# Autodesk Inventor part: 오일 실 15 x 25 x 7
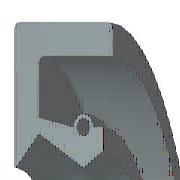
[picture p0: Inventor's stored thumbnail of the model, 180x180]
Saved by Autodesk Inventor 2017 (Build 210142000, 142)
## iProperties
Created: 2012-02
Part Number: 오일 실 15 x 25 x 7
Material: 고무
Description: 오일-실
Document SubType Name: Modeling
Standard: KS B 2804
Designer: mduedu
Standards Organization: KS
Language: ko-KR
Size Designation: D - 15 25 7
Categories: <MemberInstance><Categories><Category DisplayName="샤프트 부품" InternalName="7f7aeb1f-a693-4053-b835-cee3144e0d98" Mnemonic="SHFT"><Category DisplayName="실링" Intern
Density: 0.93 g/cm^3
Mass: 1.46464 g
Surface Area: 21.6685 cm^2
Volume: 1.57488 cm^3
Appearance: 고무 - 검은색 - 버전 1.1
IsCustomPart: 1
Author: mduedu
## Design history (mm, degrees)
revolve "본체" stored, may be unused: angle "d17" = 90 deg
revolve "스프링1" stored, may be unused: angle "d18" = 90 deg
body "Solid1"
sketch "스케치1"
  geometry: L1 (0, 12.5)-(7, 12.5); L2 (7, 10.75)-(1.75, 10.75); L3 (1.75, 9.25)-(4.9, 7.5); L4 (4.9, 7.5)-(0, 7.5); L5 (0, 0)-(9.586, 0) reference; L6 (4.9, 7.5)-(6.3, 8.375); L7 (0, 18)-(0, -3) reference; L8 (-1.941, 0)-(11.507, 0) reference; L9 (4.2, 9.6)-(1.75, 10.09); L10 (1.75, 10.09)-(1.75, 10.75); L11 (0, 12.5)-(0, 7.588); L12 (4.9, 7.5)-(0, 7.5); L13 (1.75, 9.25)-(0.152, 7.528); L14 (7, 12.5)-(7, 10.75); L15 (5.6, 9.6)-(6.3, 9.6); L16 (6.3, 9.6)-(6.3, 8.375); C1 r 0.455 at (4.9, 9.6); A1 r 0.7 centre (4.9, 9.6) between (5.6, 9.6) and (4.2, 9.6); A2 r 0.088 centre (0.088, 7.588) between (0, 7.588) and (0.152, 7.528); 1 further point
  constraints: 28 end point, 5 horizontal alignment, 5 point on line, 4 point on circle, 4 vertical alignment, 3 centre point, 3 tangent, 2 collinear, 2 horizontal, 2 perpendicular, 1 coincident, 1 parallel
  dimensions: "d0" = 25 diameter of L1 L5 (= SD2); "d1" = 1.75 distance of L1.end L2.start (= SD); "d2" = 0.91 diameter of C1 (= SPDI); "d3" = 1.4 diameter of A1 (= SPDA); "d4" = 15 diameter of L3.end L5 (= NND); "d5" = 18.5 diameter of L3.start L5 (= TKDM); "d7" = 20.18 diameter of L9.end L5 (= TKDM + 0.24 x SWDT); "d8" = 1.75 distance between parallel lines of L11 L10 (= SD); "d9" = 4.9 distance from line of L11 C1.centre (= SPDST); "d10" = 19.2 diameter of C1.centre L5 (= HLDM); "d11" = 0.0875 radius of A2 (= 0.25 x LAB); "d12" = 6.3 distance between parallel lines of L11 L16 (= SDI); "d13" = 16.75 diameter of L6.end L5 (= ABDM); "d14" = 7 distance from line of L11 L1.end (= SWDT)
fillet "모깎기1" dims "d6" = 0.3 (= RR)
other parameters: "SD2" = 25 [user parameter; used in 1 equation term], "SWDT" = 7 [user parameter; used in 2 equation terms], "RR" = 0.3 [user parameter; used in 1 equation term], "SD" = 1.75 [user parameter; used in 2 equation terms], "NND" = 15 [user parameter; used in 1 equation term], "SPDA" = 1.4 [user parameter; used in 1 equation term], "SPDI" = 0.91 [user parameter; used in 1 equation term], "TKDM" = 18.5 [user parameter; used in 2 equation terms], "HLDM" = 19.2 [user parameter; used in 1 equation term], "ABDM" = 16.75 [user parameter; used in 1 equation term], "SDI" = 6.3 [user parameter; used in 1 equation term], "SPDST" = 4.9 [user parameter; used in 1 equation term], "LAB" = 0.35 [user parameter; used in 1 equation term], "d15" = 0, "d16" = 0, "d19" = 0
